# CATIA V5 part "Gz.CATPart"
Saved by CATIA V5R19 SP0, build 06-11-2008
Part number: Gz
Publications: "H", "L", "P", "e"
Bounding box of the stored display mesh (mm): x -4000 to 0, y 0 to 300, z 0 to 300
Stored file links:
  G:\EU_thinkMotion\CFAO_2010\MMS_groupe3\MMS_groupe3\A reprendre\evulliez\evulliez\Gz.CATPart
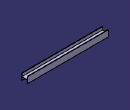
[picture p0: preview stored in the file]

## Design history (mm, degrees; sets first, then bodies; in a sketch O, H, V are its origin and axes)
Parameters
  H = 4000 mm
  L = 300 mm
  P = 300 mm
  e = 20 mm
Body1 (main body)
  Sketch1 on yz-plane, origin (0, 0, 0), H (0, 1, 0), V (0, 0, 1)
    line L1 (0, 0) -> (20, 0)
    point P1 (20, 0)
    line L2 (20, 0) -> (20, 140)
    point P2 (20, 140)
    line L3 (20, 140) -> (150, 140)
    point P3 (150, 140)
    axis line L4 (-19.3422, 150) -> (119.6708, 150)
    point P6 (20, 300)
    point P7 (0, 300)
    line L5 (0, 300) -> (20, 300)
    point P8 (20, 160)
    line L6 (20, 300) -> (20, 160)
    point P9 (150, 160)
    line L7 (20, 160) -> (150, 160)
    line L8 (0, 300) -> (0, 0)
    line L9 (150, 160) -> (150, 140)
    length L1 = 20 {= e}
    distance H L4 = 150 {= L /2}
    length L2 = 140 {= L /2 - e /2}
    length L3 = 130 {= P /2 - e}
    horizontal: L1 H, L3 H, L4 H
    vertical: L2 V, L8 V, L9 V
    symmetry: P1 P6 L4, O P7 L4, L1 L5 L4, P2 P8 L4, L2 L6 L4, P3 P9 L4, L3 L7 L4
  Pad1: profile Sketch1, direction (-1, 0, 0), length 4000 {= H}
  Mirror1: of Pad1, about face of Pad1 from Sketch1.L9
